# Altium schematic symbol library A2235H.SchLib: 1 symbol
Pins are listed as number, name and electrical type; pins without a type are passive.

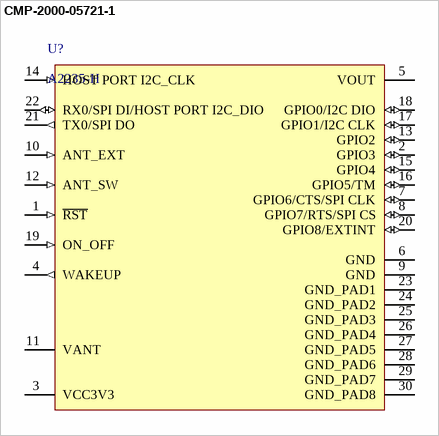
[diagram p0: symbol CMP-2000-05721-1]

## CMP-2000-05721-1
designator U?, comment A2235-H
GPS Antenna Receiver, I2C, UART, 3 to 3.6 V, -40 to 85 degC, 30-Pin SMD, RoHS, Tape and Reel; Manufacturer: Maestro Wireless Solutions; Supply Voltage Max: 3.6V; Supply Voltage Min: 3V; Protocol: NMEA,SiRFBinary; SVHC: ToBeAdvised; Frequency RF: 1.575GHz; No. of Channels: 48Channels; Module Interface: I2C,SPI,UART; Position Accuracy: 2.5m
footprint MAES-A2235-H_V (SMD, 30-Leads, Body 17.78x16.51mm)
pins: 1 ~{RST} (in) "Reset input, active low", 2 GPIO3 (io) "Leave open", 3 VCC3V3 (power) "3.0 - 3.6 V DC", 4 WAKEUP (out) "Status of digital section, Push-Pull output", 5 VOUT (power) "Permanent 1.8V voltage output for up to 20mA current max", 6 GND (power) "Ground (power supply)", 7 GPIO6/CTS/SPI CLK (io), 8 GPIO7/RTS/SPI CS (io), 9 GND (power) "Ground (power supply)", 10 ANT_EXT (in) "Antenna signal", 11 VANT (power) "Power supply antenna - provide according voltage", 12 ANT_SW (in) "Antenna switch", 13 GPIO2 (io) "Leave open", 14 HOST PORT I2C_CLK (in) "Host port I2C clock pin when module works in host port I2C mode", 15 GPIO4 (io) "External interrupt input pin- reserved for future use, leave open", 16 GPIO5/TM (io) "Time Mark - 1PPS signal", 17 GPIO1/I2C CLK (io), 18 GPIO0/I2C DIO (io), 19 ON_OFF (in) "Connect to push-pull output! This is mandatory! Connect it to WAKEUP pin for self-start mode", 20 GPIO8/EXTINT (io), 21 TX0/SPI DO (out), 22 RX0/SPI DI/HOST PORT I2C_DIO (io), 23 GND_PAD1 (power) "Ground", 24 GND_PAD2 (power) "Ground", 25 GND_PAD3 (power) "Ground", 26 GND_PAD4 (power) "Ground", 27 GND_PAD5 (power) "Ground", 28 GND_PAD6 (power) "Ground", 29 GND_PAD7 (power) "Ground", 30 GND_PAD8 (power) "Ground"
